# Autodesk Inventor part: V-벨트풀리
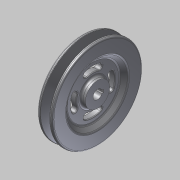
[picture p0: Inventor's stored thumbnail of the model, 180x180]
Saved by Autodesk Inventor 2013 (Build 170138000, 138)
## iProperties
Created: 2015-12
Part Number: V-벨트풀리
Document SubType Name: Modeling
Designer: mdu
Density: 8.08 g/cm^3
Material: 스테인리스강
Mass: 1092.51 g
Surface Area: 372.903 cm^2
Volume: 135.212 cm^3
Author: mdu
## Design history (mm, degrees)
sketch "스케치1"
  geometry: L1 (-10, 0)-(10, 0); L2 (-10, 0)-(-10, 16); L3 (-10, 16)-(-4, 16); L4 (-4, 16)-(-4, 35); L5 (-4, 35)-(-10, 41); L6 (-10, 41)-(-10, 59.5); L7 (-10, 59.5)-(-6.062, 59.5); L8 (-6.062, 59.5)-(-2.001, 47); L9 (-2.001, 47)-(2.001, 47); L10 (2.001, 47)-(6.062, 59.5); L11 (6.062, 59.5)-(10, 59.5); L12 (10, 59.5)-(10, 41); L13 (10, 41)-(4, 35); L14 (4, 35)-(4, 16); L15 (4, 16)-(10, 16); L16 (10, 16)-(10, 0); L17 (-4.6, 55)-(4.6, 55); 2 further points
  constraints: 34 end point, 7 parallel, 6 equal length, 5 collinear, 3 perpendicular, 2 point on line, 1 coincident, 1 horizontal, 1 midpoint
  dimensions: "d0" = 20 distance of L1.start L1.end; "d1" = 9.2 distance of L17.start L17.end; "d2" = 36 deg angle of L10 L8; "d3" = 4.5 distance between parallel lines of L7 L17; "d4" = 8 distance between parallel lines of L9 L17; "d6" = 110 diameter of L17 L1; "d7" = 32 diameter of L3 L1; "d8" = 82 diameter of L5.end L1; "d9" = 6 distance of L2.end L3.end; "d10" = 135 deg angle of L4 L5
revolve "회전1" sketch "스케치1" stored, may be unused: angle "d11" = 90 deg
fillet "모깎기1" dims "d12" = 2, "d13" = 0.5, "d14" = 1, "d15" = 3
sketch "스케치2"
  geometry: L1 (-2, 5.657)-(-2, 7.8); L2 (-2, 7.8)-(2, 7.8); L3 (2, 7.8)-(2, 5.657); A1 r 6 centre (0, 0) between (-2, 5.657) and (2, 5.657); 1 further point
  constraints: 6 end point, 2 parallel, 2 point on circle, 1 centre point, 1 coincident, 1 perpendicular, 1 vertical
  dimensions: "d16" = 12 diameter of A1; "d17" = 4 distance of L1.end L2.end; "d18" = 13.8 dimension on A1 L2 (computed from d16)
extrude "돌출1" cut sketch "스케치2" stored distance "d19" = 10; taper "d20" = 0 deg
sketch "스케치3"
  geometry: L1 (0, 0)-(0, 25.5); L2 (0, 0)-(-8.722, 23.962); C1 r 33.757 at (0, 0) reference; C2 r 19 at (0, 0) reference; A1 r 25.5 centre (0, 0) between (0, 25.5) and (-8.722, 23.962); A2 r 3.5 centre (-8.722, 23.962) between (-9.919, 27.251) and (-7.524, 20.673); A3 r 3.5 centre (8.722, 23.962) between (7.524, 20.673) and (9.919, 27.251); A4 r 29 centre (0, 0) between (9.919, 27.251) and (-9.919, 27.251); A5 r 22 centre (0, 0) between (7.524, 20.673) and (-7.524, 20.673); 1 further point
  constraints: 10 point on circle, 5 centre point, 4 coincident, 4 end point, 1 point on line, 1 symmetric about line, 1 tangent, 1 vertical, 1 other
  dimensions: "d24" = 51 diameter of A1; "d27" = 20 deg angle of L1 L2; "d29" = 7 diameter of A2
extrude "돌출2" cut sketch "스케치3" stored distance "d30" = 10; taper "d31" = 0 deg
fillet "모깎기2" dims "d32" = 1
node "솔리드1"
pattern_circular "원형 패턴1" dims angle "d34" = 360 deg
